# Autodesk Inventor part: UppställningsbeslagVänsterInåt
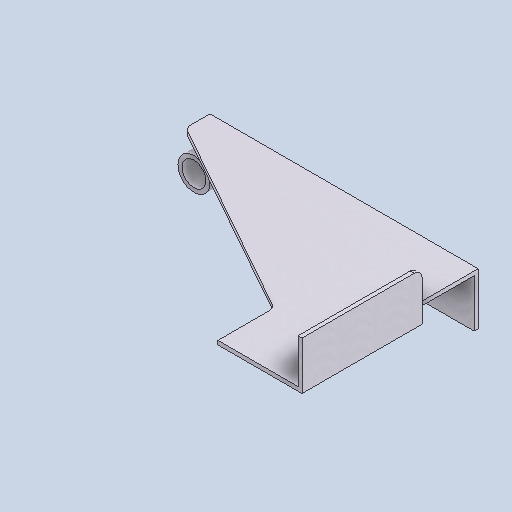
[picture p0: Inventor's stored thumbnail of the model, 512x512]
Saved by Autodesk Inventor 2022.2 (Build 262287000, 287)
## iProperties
Created: 2019-06
Part Number: UppställningsbeslagVänsterInåt
Material: Aluminum 6061, Welded
Document SubType Name: Modeling
Designer: cl
Density: 2.7 g/cm^3
Appearance: Weld - Aluminum
Author: cl
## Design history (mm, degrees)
sketch "Sketch1"
  geometry: L1 (0, 0)-(100, 0); L2 (100, 0)-(100, -70); L3 (100, -70)-(350, -210); L4 (350, -210)-(350, -240); L5 (350, -240)-(15, -240); L6 (15, -240)-(15, -150); L7 (15, -150)-(-5, -150); L8 (-5, -150)-(-5, 0); L9 (-5, 0)-(0, 0)
  constraints: 18 end point, 3 perpendicular, 3 vertical, 1 horizontal, 1 parallel
  dimensions: "d3" = 100 distance of L1.start L1.end; "d4" = 70 distance of L1.end L2.end; "d5" = 335 distance of L4.end L5.end; "d6" = 30 distance of L3.end L4.end; "d8" = 240 distance between parallel lines of L5 L1; "d9" = 90 distance of L5.end L6.end; "d10" = 20 distance of L6.end L7.end; "d11" = 350 distance from line of L4 L1.start
extrude "Extrusion1" new body sketch "Sketch1" distance "d12" = 5; taper "d13" = 0 deg
fillet "Fillet1" dims "d14" = 10
sketch "Sketch2"
  geometry: L1 (5, 150)-(-5, 150) reference; L2 (5, 150)-(0, 150); L3 (0, 150)-(0, 0); L4 (0, 0)-(5, 0); L5 (5, 0)-(5, 150); 1 further point
  constraints: 8 end point, 2 parallel, 1 horizontal, 1 perpendicular
extrude "Extrusion2" join sketch "Sketch2" distance "d15" = 55; taper "d16" = 0 deg
fillet "Fillet2" dims "d17" = 10
sketch "Sketch3"
  geometry: L1 (-15, -240)-(-350, -240) reference; L2 (-350, -240)-(-350, -215.861) reference; L3 (-15, -240)-(-350, -240); L4 (-350, -240)-(-350, -235); L5 (-350, -235)-(-15, -235); L6 (-15, -235)-(-15, -240); 2 further points
  constraints: 8 end point, 2 parallel, 1 horizontal, 1 perpendicular, 1 point on line
  dimensions: "d18" = 5 distance between parallel lines of L1 L5
extrude "Extrusion3" join sketch "Sketch3" distance "d19" = 60; taper "d20" = 0 deg
sketch "Sketch4"
  geometry: L1 (0, 0)-(0, -60) reference; L2 (335, -60)-(0, -60) reference; C1 r 20 at (20, -30); C2 r 15 at (20, -30); 1 further point
  constraints: 2 centre point, 1 coincident, 1 tangent
  dimensions: "d21" = 40 diameter of C1; "d22" = 30 diameter of C2; "d23" = 30 distance from line of L2 C1.centre
extrude "Extrusion4" join sketch "Sketch4" distance "d24" = 35; taper "d25" = 0 deg
body "Solid1"
